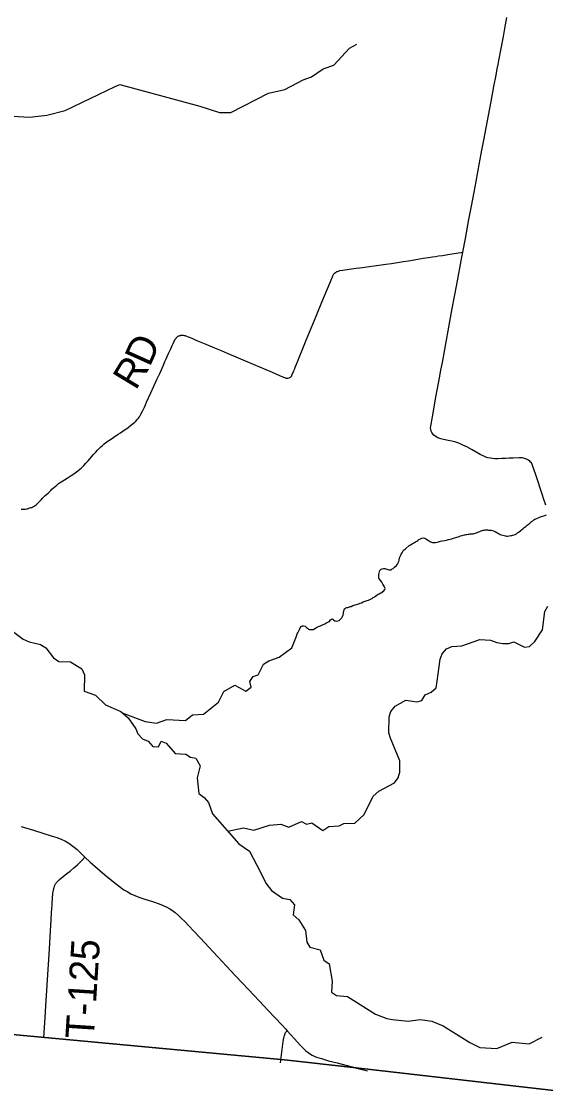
# Model space of a CAD drawing. Extents: x 1410790 to 1770854, y 448063 to 770588.
# Drawn here: x 1542911 to 1548426, y 575317 to 586651 of the extents above; entities that cross this region are included whole.
import ezdxf

# ---------------------------------------------------------------- set-up
doc = ezdxf.new("R2010")
doc.units = 0
for name, color, linetype in [('GM_X_Adjacent_County', 7, 'Continuous'), ('GM_X_County', 7, 'Continuous'), ('GM_X_County_Road', 7, 'Continuous'), ('GM_X_Minor_River', 7, 'Continuous'), ('GM_X_Township', 7, 'Continuous'), ('GM_X_Township_Road', 7, 'Continuous'), ('GM_X_Township_Road_Text', 7, 'Continuous')]:
    doc.layers.add(name, color=color, linetype=linetype)

msp = doc.modelspace()

# ---------------------------------------------------------------- linework, layer by layer
at = {"layer": 'GM_X_Adjacent_County'}
msp.add_lwpolyline([(1491208, 581151), (1492956, 580980), (1498216, 580440), (1499383, 580320), (1499831, 580274), (1508028, 579406), (1509752, 579223), (1510502, 579144), (1513514, 578840), (1514569, 578744), (1516950, 578527), (1518829, 578332), (1524308, 577745), (1526680, 577524), (1529627, 577249), (1531677, 577058), (1536645, 576561), (1543157, 575958), (1545678, 575724), (1546403, 575642), (1549246, 575317)], dxfattribs=at)
at = {"layer": 'GM_X_County'}
msp.add_lwpolyline([(1526680, 577524), (1529627, 577249), (1531677, 577058), (1536645, 576561), (1543157, 575958), (1545678, 575724), (1546403, 575642), (1549246, 575317)], dxfattribs=at)
at = {"layer": 'GM_X_County_Road'}
for points in [[(1542908, 578178), (1543037, 578140), (1543235, 578079), (1543284, 578063), (1543329, 578046), (1543373, 578024), (1543409, 578002), (1543438, 577983), (1543465, 577963), (1543496, 577936), (1543527, 577907), (1543576, 577858)], [(1543576, 577858), (1543633, 577804), (1543682, 577760), (1543788, 577672), (1543880, 577595), (1543941, 577548), (1543988, 577514), (1544022, 577494), (1544063, 577472), (1544103, 577454), (1544146, 577436), (1544199, 577419), (1544301, 577387), (1544359, 577366), (1544403, 577348), (1544439, 577330), (1544471, 577312), (1544499, 577295), (1544528, 577273), (1544563, 577244), (1544593, 577216), (1544629, 577180), (1544673, 577135), (1544726, 577077), (1544796, 577003), (1544838, 576957), (1544977, 576808), (1545069, 576710), (1545165, 576608), (1545235, 576534), (1545300, 576465), (1545356, 576404), (1545416, 576340), (1545504, 576247), (1545576, 576170), (1545653, 576089), (1545692, 576047), (1545708, 576030)], [(1545708, 576030), (1545786, 575944), (1545845, 575878), (1545879, 575843), (1545905, 575818), (1545928, 575800), (1545952, 575784), (1545971, 575772), (1545991, 575763), (1546015, 575753), (1546039, 575746), (1546068, 575736), (1546099, 575726), (1546143, 575714), (1546232, 575691), (1546326, 575666), (1546393, 575648), (1546404, 575645)], [(1546404, 575645), (1546437, 575637), (1546553, 575609)]]:
    msp.add_lwpolyline(points, dxfattribs=at)
at = {"layer": 'GM_X_Minor_River'}
for points in [[(1545874, 586039), (1545964, 586069), (1546086, 586154), (1546197, 586192), (1546362, 586372), (1546439, 586413)], [(1542121, 585654), (1542344, 585748), (1542410, 585743), (1542701, 585662), (1542995, 585646), (1543178, 585666), (1543369, 585714), (1543895, 585966), (1543946, 585989), (1544789, 585762), (1544996, 585693), (1545116, 585695), (1545511, 585897), (1545684, 585935), (1545874, 586039)], [(1548150, 581281), (1548164, 581291), (1548174, 581301), (1548192, 581315), (1548202, 581325), (1548219, 581337), (1548235, 581351), (1548245, 581359), (1548261, 581371), (1548271, 581381), (1548281, 581389), (1548293, 581396), (1548305, 581406), (1548315, 581412), (1548334, 581420), (1548348, 581426), (1548366, 581434), (1548382, 581442), (1548394, 581446), (1548408, 581450), (1548436, 581458)], [(1546768, 580884), (1546780, 580881), (1546790, 580881), (1546802, 580881), (1546814, 580891), (1546824, 580895), (1546838, 580909), (1546857, 580927), (1546869, 580941), (1546875, 580953), (1546883, 580969), (1546887, 580983), (1546891, 581005), (1546900, 581029), (1546908, 581047), (1546918, 581061), (1546926, 581075), (1546932, 581087), (1546944, 581095), (1546954, 581103), (1546991, 581137), (1547007, 581145), (1547023, 581155), (1547035, 581161), (1547047, 581169), (1547059, 581174), (1547071, 581182), (1547081, 581188), (1547095, 581198), (1547112, 581208), (1547124, 581214), (1547142, 581216), (1547156, 581214), (1547168, 581208), (1547184, 581196), (1547204, 581181), (1547216, 581175), (1547228, 581171), (1547238, 581169), (1547254, 581167), (1547270, 581169), (1547286, 581173), (1547302, 581175), (1547320, 581181), (1547340, 581184), (1547368, 581190), (1547386, 581194), (1547407, 581200), (1547423, 581204), (1547439, 581208), (1547455, 581214), (1547471, 581218), (1547483, 581222), (1547517, 581231), (1547533, 581237), (1547551, 581241), (1547561, 581245), (1547578, 581249), (1547588, 581251), (1547600, 581253), (1547612, 581255), (1547624, 581257), (1547634, 581259), (1547654, 581259), (1547664, 581260), (1547674, 581262), (1547686, 581266), (1547702, 581270), (1547716, 581276), (1547734, 581284), (1547748, 581290), (1547759, 581294), (1547771, 581298), (1547781, 581298), (1547791, 581300), (1547801, 581302), (1547815, 581302), (1547827, 581299), (1547839, 581299), (1547855, 581297), (1547869, 581293), (1547887, 581287), (1547897, 581283), (1547915, 581273), (1547925, 581267), (1547939, 581258), (1547949, 581254), (1547961, 581250), (1547991, 581240), (1548005, 581238), (1548017, 581236), (1548027, 581236), (1548043, 581238), (1548061, 581240), (1548071, 581241), (1548083, 581245), (1548096, 581249), (1548108, 581253), (1548120, 581261), (1548136, 581273), (1548150, 581281)], [(1545757, 580059), (1545804, 580184), (1545812, 580206), (1545818, 580216), (1545822, 580226), (1545832, 580244), (1545840, 580258), (1545844, 580270), (1545855, 580284), (1545869, 580292), (1545879, 580292), (1545897, 580288), (1545911, 580273), (1545921, 580265), (1545933, 580257), (1545943, 580253), (1545957, 580253), (1545971, 580251), (1545983, 580251), (1545999, 580263), (1546017, 580273), (1546031, 580279), (1546045, 580287), (1546059, 580292), (1546080, 580302), (1546104, 580312), (1546126, 580326), (1546142, 580334), (1546154, 580338), (1546162, 580354), (1546174, 580362), (1546184, 580366), (1546194, 580354), (1546208, 580344), (1546228, 580339), (1546242, 580345), (1546255, 580347), (1546267, 580361), (1546281, 580375), (1546289, 580389), (1546297, 580407), (1546301, 580421), (1546301, 580435), (1546303, 580445), (1546307, 580459), (1546314, 580471), (1546324, 580479), (1546334, 580483), (1546346, 580485), (1546356, 580489), (1546370, 580493), (1546380, 580495), (1546400, 580505), (1546414, 580509), (1546424, 580511), (1546436, 580517), (1546448, 580520), (1546460, 580524), (1546475, 580528), (1546489, 580534), (1546507, 580542), (1546527, 580552), (1546551, 580556), (1546563, 580562), (1546577, 580568), (1546591, 580574), (1546603, 580580), (1546613, 580588), (1546626, 580596), (1546650, 580613), (1546666, 580623), (1546676, 580629), (1546694, 580637), (1546706, 580643), (1546716, 580653), (1546726, 580661), (1546737, 580673), (1546739, 580685), (1546731, 580703), (1546723, 580719), (1546715, 580731), (1546703, 580750), (1546689, 580768), (1546683, 580778), (1546671, 580792), (1546673, 580804), (1546673, 580818), (1546673, 580832), (1546675, 580846), (1546678, 580860), (1546682, 580872), (1546696, 580886), (1546706, 580892), (1546722, 580896), (1546736, 580896), (1546746, 580892), (1546758, 580888), (1546768, 580884)], [(1545726, 578172), (1545857, 578232), (1545910, 578203), (1545967, 578219), (1546083, 578136), (1546146, 578179), (1546253, 578187), (1546305, 578210), (1546420, 578213), (1546518, 578305), (1546612, 578497), (1546671, 578550), (1546837, 578638), (1546877, 578692), (1546894, 578752), (1546892, 578870), (1546795, 579109), (1546776, 579166), (1546782, 579334), (1546799, 579388), (1546843, 579447), (1546956, 579510), (1547072, 579490), (1547126, 579504), (1547160, 579566), (1547222, 579592), (1547277, 579639), (1547287, 579709), (1547318, 579941), (1547339, 579995), (1547384, 580048), (1547439, 580073), (1547545, 580080), (1547735, 580148), (1547849, 580139), (1547913, 580114), (1547979, 580106), (1548041, 580105), (1548095, 580124), (1548206, 580065), (1548258, 580072), (1548314, 580125), (1548394, 580249), (1548419, 580443), (1548452, 580498)], [(1542815, 580235), (1542928, 580152), (1542992, 580121), (1543111, 580094), (1543167, 580061), (1543247, 579955), (1543302, 579917), (1543426, 579911), (1543547, 579840), (1543574, 579775), (1543571, 579603), (1543688, 579560), (1543794, 579461), (1543955, 579390), (1544032, 579322), (1544114, 579208), (1544135, 579153), (1544184, 579100), (1544243, 579076), (1544293, 579021), (1544353, 579018), (1544380, 579076), (1544433, 579056), (1544530, 578948), (1544640, 578940), (1544691, 578908), (1544747, 578897), (1544793, 578818), (1544759, 578690), (1544776, 578525), (1544835, 578486), (1544880, 578433), (1544922, 578311), (1545198, 577996), (1545311, 577920), (1545427, 577699), (1545483, 577583), (1545541, 577505), (1545658, 577425), (1545713, 577415)], [(1543970, 579376), (1544213, 579284), (1544331, 579267), (1544442, 579305), (1544638, 579295), (1544712, 579353), (1544828, 579363), (1544983, 579488), (1545041, 579601), (1545155, 579665), (1545272, 579602), (1545327, 579645), (1545316, 579704), (1545351, 579757), (1545403, 579776), (1545459, 579887), (1545514, 579924), (1545623, 579962), (1545757, 580059)], [(1545082, 578129), (1545246, 578166), (1545355, 578140), (1545521, 578194), (1545639, 578202), (1545726, 578172)], [(1545713, 577415), (1545735, 577410)], [(1545735, 577410), (1545784, 577355), (1545770, 577251), (1545829, 577197), (1545899, 577083), (1545916, 576963), (1545945, 576910), (1546056, 576881), (1546092, 576774), (1546150, 576734), (1546180, 576553), (1546175, 576437), (1546227, 576399), (1546343, 576391), (1546637, 576205), (1546758, 576158), (1546816, 576147), (1546980, 576129), (1547109, 576148), (1547229, 576129), (1547350, 576080), (1547631, 575907), (1547734, 575854), (1547914, 575842), (1548077, 575909), (1548255, 575890), (1548393, 575961)]]:
    msp.add_lwpolyline(points, dxfattribs=at)
at = {"layer": 'GM_X_Township'}
msp.add_lwpolyline([(1549246, 575317), (1546403, 575642), (1545678, 575724), (1543157, 575958), (1536645, 576561), (1531677, 577058), (1529627, 577249), (1530071, 582399), (1530526, 587739)], dxfattribs=at)
at = {"layer": 'GM_X_Township_Road'}
for points in [[(1547556, 584222), (1547584, 584366), (1547620, 584566), (1547647, 584707), (1547675, 584856), (1547696, 584969), (1547733, 585165), (1547758, 585297), (1547778, 585404), (1547825, 585662), (1547853, 585810), (1547882, 585968), (1547906, 586087), (1547919, 586154), (1547927, 586199), (1547935, 586241), (1547984, 586495), (1548000, 586579), (1548020, 586692)], [(1545727, 582901), (1545734, 582904), (1545741, 582908), (1545747, 582913), (1545752, 582918), (1545755, 582923), (1545758, 582928), (1545765, 582946), (1545776, 582970), (1545782, 582986), (1545787, 582998), (1545796, 583022), (1545805, 583044), (1545822, 583086), (1545833, 583114), (1545873, 583211), (1545909, 583299), (1546013, 583551), (1546072, 583697), (1546128, 583830), (1546183, 583963), (1546188, 583973), (1546192, 583983), (1546196, 583989), (1546200, 583995), (1546207, 584003), (1546215, 584009), (1546222, 584014), (1546231, 584019), (1546237, 584022), (1546246, 584025), (1546253, 584028), (1546261, 584030), (1546292, 584036), (1546361, 584045), (1546409, 584051), (1546435, 584054), (1546468, 584058), (1546501, 584063), (1546546, 584069), (1546647, 584084), (1546747, 584098), (1546806, 584106), (1546933, 584125), (1546984, 584133), (1547043, 584143), (1547140, 584159), (1547195, 584168), (1547237, 584174), (1547269, 584179), (1547302, 584184), (1547341, 584190), (1547399, 584199), (1547464, 584209), (1547489, 584213), (1547556, 584222)], [(1548429, 581562), (1548406, 581630), (1548394, 581668), (1548380, 581709), (1548366, 581752), (1548352, 581796), (1548324, 581879), (1548286, 581990), (1548278, 582005), (1548270, 582015), (1548260, 582025), (1548249, 582033), (1548241, 582039), (1548235, 582042), (1548226, 582046), (1548217, 582050), (1548207, 582053), (1548195, 582056), (1548181, 582058), (1548168, 582059), (1548148, 582060), (1548086, 582057), (1548063, 582056), (1548044, 582055), (1548005, 582053), (1547966, 582051), (1547927, 582049), (1547911, 582049), (1547892, 582050), (1547869, 582051), (1547848, 582054), (1547821, 582059), (1547797, 582067), (1547776, 582076), (1547738, 582094), (1547653, 582142), (1547598, 582174), (1547557, 582194), (1547516, 582212), (1547483, 582223), (1547442, 582235), (1547402, 582243), (1547352, 582252), (1547326, 582259), (1547292, 582271), (1547274, 582281), (1547252, 582299), (1547238, 582316), (1547231, 582327), (1547223, 582341), (1547218, 582359), (1547217, 582377), (1547219, 582394), (1547237, 582492), (1547277, 582717), (1547290, 582790), (1547304, 582864), (1547310, 582900), (1547326, 582981), (1547341, 583061), (1547444, 583631), (1547493, 583885), (1547547, 584172), (1547556, 584222)], [(1543393, 581844), (1543433, 581872), (1543462, 581892), (1543517, 581934), (1543526, 581941), (1543538, 581951), (1543554, 581966), (1543568, 581980), (1543589, 582002), (1543611, 582027), (1543670, 582094), (1543689, 582116), (1543710, 582139), (1543727, 582156), (1543746, 582174), (1543763, 582189), (1543782, 582206), (1543824, 582237), (1543837, 582246), (1543928, 582308), (1543952, 582324), (1543980, 582343), (1544008, 582362), (1544032, 582379), (1544059, 582399), (1544090, 582423), (1544102, 582434), (1544115, 582446), (1544129, 582463), (1544141, 582478), (1544152, 582492), (1544161, 582506), (1544168, 582517), (1544185, 582549), (1544204, 582591), (1544216, 582618), (1544228, 582645), (1544273, 582742), (1544336, 582883), (1544366, 582948), (1544404, 583034), (1544421, 583072), (1544433, 583101), (1544456, 583151), (1544471, 583184), (1544481, 583207), (1544497, 583243), (1544506, 583262), (1544514, 583280), (1544520, 583289), (1544525, 583299), (1544530, 583307), (1544532, 583311), (1544536, 583316), (1544541, 583323), (1544546, 583329), (1544553, 583334), (1544560, 583339), (1544566, 583342), (1544571, 583344), (1544576, 583346), (1544583, 583348), (1544589, 583350), (1544594, 583350), (1544600, 583350), (1544607, 583350), (1544614, 583349), (1544622, 583348), (1544634, 583345), (1544647, 583341), (1544665, 583334), (1544680, 583328), (1544765, 583292), (1544852, 583255), (1544943, 583218), (1545012, 583189), (1545076, 583162), (1545284, 583073), (1545550, 582960), (1545628, 582925), (1545667, 582909), (1545678, 582904), (1545685, 582902), (1545690, 582900), (1545696, 582899), (1545703, 582898), (1545708, 582898), (1545715, 582898), (1545727, 582901)], [(1542906, 581519), (1542926, 581519), (1542939, 581519), (1542951, 581520), (1542963, 581522), (1542975, 581524), (1542987, 581528), (1543000, 581532), (1543010, 581535), (1543019, 581538), (1543031, 581544), (1543043, 581550), (1543055, 581558), (1543065, 581566), (1543084, 581583), (1543104, 581602), (1543118, 581616), (1543133, 581633), (1543161, 581661), (1543190, 581689), (1543218, 581716), (1543230, 581728), (1543281, 581772), (1543294, 581782), (1543301, 581788), (1543311, 581795), (1543319, 581801), (1543328, 581806), (1543362, 581826), (1543393, 581844)], [(1543168, 576293), (1543192, 576673), (1543206, 576889), (1543214, 577020), (1543223, 577197), (1543226, 577269), (1543232, 577356), (1543237, 577442), (1543239, 577460), (1543240, 577478), (1543243, 577492), (1543246, 577509), (1543250, 577525), (1543253, 577538), (1543257, 577550), (1543262, 577562), (1543265, 577569), (1543269, 577575), (1543274, 577582), (1543278, 577588), (1543283, 577594), (1543289, 577600), (1543310, 577620), (1543389, 577683), (1543423, 577710), (1543463, 577743), (1543505, 577779), (1543537, 577811), (1543549, 577825), (1543576, 577858)], [(1543146, 575959), (1543161, 576168), (1543168, 576293)], [(1545638, 575693), (1545666, 575916), (1545673, 575955), (1545675, 575966), (1545679, 575978), (1545683, 575991), (1545687, 576001), (1545691, 576010), (1545697, 576017), (1545700, 576021), (1545703, 576025), (1545708, 576030)]]:
    msp.add_lwpolyline(points, dxfattribs=at)

# ---------------------------------------------------------------- texts
at = {"layer": 'GM_X_Township_Road_Text'}
for s, rotation, p in [('D', 65.8484, (1544260, 583007)), ('R', 58.7782, (1544113, 582761)), ('T-125', 86.3533, (1543671, 575938))]:
    msp.add_text(s, height=300, rotation=rotation, dxfattribs=at).set_placement(p)

doc.saveas('drawing.dxf')
